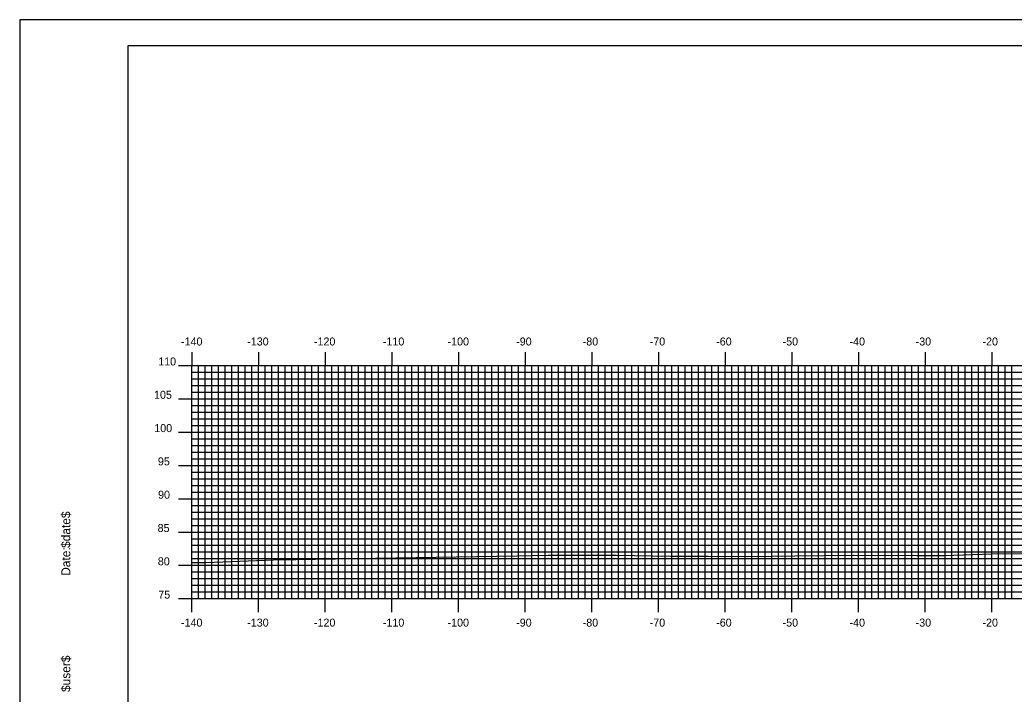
# Model space of a CAD drawing. Extents: x 852542 to 852886, y 364366 to 364586.
# Drawn here: x 852542.4 to 852691.5, y 364484.5 to 364585.7 of the extents above; entities that cross this region are included whole.
import ezdxf

# ---------------------------------------------------------------- set-up
doc = ezdxf.new("R2010")
doc.units = 0
for name, color, linetype in [('BORDER', 7, 'Continuous'), ('H_V ANNOTATION', 7, 'Continuous'), ('MAJOR', 7, 'Continuous'), ('MINOR', 7, 'Continuous'), ('PLOT BOUNDARY', 7, 'Continuous'), ('S_Roadway_Centerline', 7, 'Continuous')]:
    doc.layers.add(name, color=color, linetype=linetype)

msp = doc.modelspace()

# ---------------------------------------------------------------- linework, layer by layer
at = {"layer": 'BORDER'}
msp.add_lwpolyline([(852558.58, 364371.79), (852878.58, 364371.79), (852878.58, 364581.79), (852558.58, 364581.79)], close=True, dxfattribs=at)
at = {"layer": 'MAJOR'}
for p, q in [((852568.18, 364535.79), (852568.18, 364533.79)), ((852578.18, 364535.79), (852578.18, 364533.79)), ((852588.18, 364535.79), (852588.18, 364533.79)), ((852598.18, 364535.79), (852598.18, 364533.79)), ((852608.18, 364535.79), (852608.18, 364533.79)), ((852618.18, 364535.79), (852618.18, 364533.79)), ((852628.18, 364535.79), (852628.18, 364533.79)), ((852638.18, 364535.79), (852638.18, 364533.79)), ((852648.18, 364535.79), (852648.18, 364533.79)), ((852658.18, 364535.79), (852658.18, 364533.79)), ((852668.18, 364535.79), (852668.18, 364533.79)), ((852678.18, 364535.79), (852678.18, 364533.79)), ((852688.18, 364535.79), (852688.18, 364533.79)), ((852566.17, 364533.79), (852568.18, 364533.79)), ((852568.18, 364533.79), (852848.18, 364533.79)), ((852568.18, 364498.79), (852568.18, 364533.79)), ((852568.18, 364498.79), (852568.18, 364533.79)), ((852568.18, 364533.79), (852848.18, 364533.79)), ((852578.18, 364498.79), (852578.18, 364533.79)), ((852588.18, 364498.79), (852588.18, 364533.79)), ((852598.18, 364498.79), (852598.18, 364533.79)), ((852608.18, 364498.79), (852608.18, 364533.79)), ((852618.18, 364498.79), (852618.18, 364533.79)), ((852628.18, 364498.79), (852628.18, 364533.79)), ((852638.18, 364498.79), (852638.18, 364533.79)), ((852648.18, 364498.79), (852648.18, 364533.79)), ((852658.18, 364498.79), (852658.18, 364533.79)), ((852668.18, 364498.79), (852668.18, 364533.79)), ((852678.18, 364498.79), (852678.18, 364533.79)), ((852688.18, 364498.79), (852688.18, 364533.79)), ((852566.17, 364528.79), (852568.18, 364528.79)), ((852568.18, 364528.79), (852848.18, 364528.79)), ((852566.17, 364523.79), (852568.18, 364523.79)), ((852568.18, 364523.79), (852848.18, 364523.79)), ((852566.17, 364518.79), (852568.18, 364518.79)), ((852568.18, 364518.79), (852848.18, 364518.79)), ((852566.17, 364513.79), (852568.18, 364513.79)), ((852568.18, 364513.79), (852848.18, 364513.79)), ((852566.17, 364508.79), (852568.18, 364508.79)), ((852568.18, 364508.79), (852848.18, 364508.79)), ((852566.17, 364503.79), (852568.18, 364503.79)), ((852568.18, 364503.79), (852848.18, 364503.79)), ((852566.17, 364498.79), (852568.18, 364498.79)), ((852568.18, 364498.79), (852848.18, 364498.79)), ((852568.18, 364498.79), (852848.18, 364498.79)), ((852568.18, 364496.78), (852568.18, 364498.79)), ((852578.18, 364496.78), (852578.18, 364498.79)), ((852588.18, 364496.78), (852588.18, 364498.79)), ((852598.18, 364496.78), (852598.18, 364498.79)), ((852608.18, 364496.78), (852608.18, 364498.79)), ((852618.18, 364496.78), (852618.18, 364498.79)), ((852628.18, 364496.78), (852628.18, 364498.79)), ((852638.18, 364496.78), (852638.18, 364498.79)), ((852648.18, 364496.78), (852648.18, 364498.79)), ((852658.18, 364496.78), (852658.18, 364498.79)), ((852668.18, 364496.78), (852668.18, 364498.79)), ((852678.18, 364496.78), (852678.18, 364498.79)), ((852688.18, 364496.78), (852688.18, 364498.79))]:
    msp.add_line(p, q, dxfattribs=at)
at = {"layer": 'MINOR'}
for p, q in [((852569.18, 364498.79), (852569.18, 364533.79)), ((852570.18, 364498.79), (852570.18, 364533.79)), ((852571.18, 364498.79), (852571.18, 364533.79)), ((852572.18, 364498.79), (852572.18, 364533.79)), ((852573.18, 364498.79), (852573.18, 364533.79)), ((852574.18, 364498.79), (852574.18, 364533.79)), ((852575.18, 364498.79), (852575.18, 364533.79)), ((852576.18, 364498.79), (852576.18, 364533.79)), ((852577.18, 364498.79), (852577.18, 364533.79)), ((852579.18, 364498.79), (852579.18, 364533.79)), ((852580.18, 364498.79), (852580.18, 364533.79)), ((852581.18, 364498.79), (852581.18, 364533.79)), ((852582.18, 364498.79), (852582.18, 364533.79)), ((852583.18, 364498.79), (852583.18, 364533.79)), ((852584.18, 364498.79), (852584.18, 364533.79)), ((852585.18, 364498.79), (852585.18, 364533.79)), ((852586.18, 364498.79), (852586.18, 364533.79)), ((852587.18, 364498.79), (852587.18, 364533.79)), ((852589.18, 364498.79), (852589.18, 364533.79)), ((852590.18, 364498.79), (852590.18, 364533.79)), ((852591.18, 364498.79), (852591.18, 364533.79)), ((852592.18, 364498.79), (852592.18, 364533.79)), ((852593.18, 364498.79), (852593.18, 364533.79)), ((852594.18, 364498.79), (852594.18, 364533.79)), ((852595.18, 364498.79), (852595.18, 364533.79)), ((852596.18, 364498.79), (852596.18, 364533.79)), ((852597.18, 364498.79), (852597.18, 364533.79)), ((852599.18, 364498.79), (852599.18, 364533.79)), ((852600.18, 364498.79), (852600.18, 364533.79)), ((852601.18, 364498.79), (852601.18, 364533.79)), ((852602.18, 364498.79), (852602.18, 364533.79)), ((852603.18, 364498.79), (852603.18, 364533.79)), ((852604.18, 364498.79), (852604.18, 364533.79)), ((852605.18, 364498.79), (852605.18, 364533.79)), ((852606.18, 364498.79), (852606.18, 364533.79)), ((852607.18, 364498.79), (852607.18, 364533.79)), ((852609.18, 364498.79), (852609.18, 364533.79)), ((852610.18, 364498.79), (852610.18, 364533.79)), ((852611.18, 364498.79), (852611.18, 364533.79)), ((852612.18, 364498.79), (852612.18, 364533.79)), ((852613.18, 364498.79), (852613.18, 364533.79)), ((852614.18, 364498.79), (852614.18, 364533.79)), ((852615.18, 364498.79), (852615.18, 364533.79)), ((852616.18, 364498.79), (852616.18, 364533.79)), ((852617.18, 364498.79), (852617.18, 364533.79)), ((852619.18, 364498.79), (852619.18, 364533.79)), ((852620.18, 364498.79), (852620.18, 364533.79)), ((852621.18, 364498.79), (852621.18, 364533.79)), ((852622.18, 364498.79), (852622.18, 364533.79)), ((852623.18, 364498.79), (852623.18, 364533.79)), ((852624.18, 364498.79), (852624.18, 364533.79)), ((852625.18, 364498.79), (852625.18, 364533.79)), ((852626.18, 364498.79), (852626.18, 364533.79)), ((852627.18, 364498.79), (852627.18, 364533.79)), ((852629.18, 364498.79), (852629.18, 364533.79)), ((852630.18, 364498.79), (852630.18, 364533.79)), ((852631.18, 364498.79), (852631.18, 364533.79)), ((852632.18, 364498.79), (852632.18, 364533.79)), ((852633.18, 364498.79), (852633.18, 364533.79)), ((852634.18, 364498.79), (852634.18, 364533.79)), ((852635.18, 364498.79), (852635.18, 364533.79)), ((852636.18, 364498.79), (852636.18, 364533.79)), ((852637.18, 364498.79), (852637.18, 364533.79)), ((852639.18, 364498.79), (852639.18, 364533.79)), ((852640.18, 364498.79), (852640.18, 364533.79)), ((852641.18, 364498.79), (852641.18, 364533.79)), ((852642.18, 364498.79), (852642.18, 364533.79)), ((852643.18, 364498.79), (852643.18, 364533.79)), ((852644.18, 364498.79), (852644.18, 364533.79)), ((852645.18, 364498.79), (852645.18, 364533.79)), ((852646.18, 364498.79), (852646.18, 364533.79)), ((852647.18, 364498.79), (852647.18, 364533.79)), ((852649.18, 364498.79), (852649.18, 364533.79)), ((852650.18, 364498.79), (852650.18, 364533.79)), ((852651.18, 364498.79), (852651.18, 364533.79)), ((852652.18, 364498.79), (852652.18, 364533.79)), ((852653.18, 364498.79), (852653.18, 364533.79)), ((852654.18, 364498.79), (852654.18, 364533.79)), ((852655.18, 364498.79), (852655.18, 364533.79)), ((852656.18, 364498.79), (852656.18, 364533.79)), ((852657.18, 364498.79), (852657.18, 364533.79)), ((852659.18, 364498.79), (852659.18, 364533.79)), ((852660.18, 364498.79), (852660.18, 364533.79)), ((852661.18, 364498.79), (852661.18, 364533.79)), ((852662.18, 364498.79), (852662.18, 364533.79)), ((852663.18, 364498.79), (852663.18, 364533.79)), ((852664.18, 364498.79), (852664.18, 364533.79)), ((852665.18, 364498.79), (852665.18, 364533.79)), ((852666.18, 364498.79), (852666.18, 364533.79)), ((852667.18, 364498.79), (852667.18, 364533.79)), ((852669.18, 364498.79), (852669.18, 364533.79)), ((852670.18, 364498.79), (852670.18, 364533.79)), ((852671.18, 364498.79), (852671.18, 364533.79)), ((852672.18, 364498.79), (852672.18, 364533.79)), ((852673.18, 364498.79), (852673.18, 364533.79)), ((852674.18, 364498.79), (852674.18, 364533.79)), ((852675.18, 364498.79), (852675.18, 364533.79)), ((852676.18, 364498.79), (852676.18, 364533.79)), ((852677.18, 364498.79), (852677.18, 364533.79)), ((852679.18, 364498.79), (852679.18, 364533.79)), ((852680.18, 364498.79), (852680.18, 364533.79)), ((852681.18, 364498.79), (852681.18, 364533.79)), ((852682.18, 364498.79), (852682.18, 364533.79)), ((852683.18, 364498.79), (852683.18, 364533.79)), ((852684.18, 364498.79), (852684.18, 364533.79)), ((852685.18, 364498.79), (852685.18, 364533.79)), ((852686.18, 364498.79), (852686.18, 364533.79)), ((852687.18, 364498.79), (852687.18, 364533.79)), ((852689.18, 364498.79), (852689.18, 364533.79)), ((852690.18, 364498.79), (852690.18, 364533.79)), ((852691.18, 364498.79), (852691.18, 364533.79)), ((852568.18, 364532.79), (852848.18, 364532.79)), ((852568.18, 364532.79), (852570.18, 364532.79)), ((852568.18, 364531.79), (852848.18, 364531.79)), ((852568.18, 364531.79), (852570.18, 364531.79)), ((852568.18, 364530.79), (852848.18, 364530.79)), ((852568.18, 364530.79), (852570.18, 364530.79)), ((852568.18, 364529.79), (852848.18, 364529.79)), ((852568.18, 364529.79), (852570.18, 364529.79)), ((852568.18, 364527.79), (852848.18, 364527.79)), ((852568.18, 364527.79), (852570.18, 364527.79)), ((852568.18, 364526.79), (852848.18, 364526.79)), ((852568.18, 364526.79), (852570.18, 364526.79)), ((852568.18, 364525.79), (852848.18, 364525.79)), ((852568.18, 364525.79), (852570.18, 364525.79)), ((852568.18, 364524.79), (852848.18, 364524.79)), ((852568.18, 364524.79), (852570.18, 364524.79)), ((852568.18, 364522.79), (852848.18, 364522.79)), ((852568.18, 364522.79), (852570.18, 364522.79)), ((852568.18, 364521.79), (852848.18, 364521.79)), ((852568.18, 364521.79), (852570.18, 364521.79)), ((852568.18, 364520.79), (852848.18, 364520.79)), ((852568.18, 364520.79), (852570.18, 364520.79)), ((852568.18, 364519.79), (852848.18, 364519.79)), ((852568.18, 364519.79), (852570.18, 364519.79)), ((852568.18, 364517.79), (852848.18, 364517.79)), ((852568.18, 364517.79), (852570.18, 364517.79)), ((852568.18, 364516.79), (852848.18, 364516.79)), ((852568.18, 364516.79), (852570.18, 364516.79)), ((852568.18, 364515.79), (852848.18, 364515.79)), ((852568.18, 364515.79), (852570.18, 364515.79)), ((852568.18, 364514.79), (852848.18, 364514.79)), ((852568.18, 364514.79), (852570.18, 364514.79)), ((852568.18, 364512.79), (852848.18, 364512.79)), ((852568.18, 364512.79), (852570.18, 364512.79)), ((852568.18, 364511.79), (852848.18, 364511.79)), ((852568.18, 364511.79), (852570.18, 364511.79)), ((852568.18, 364510.79), (852848.18, 364510.79)), ((852568.18, 364510.79), (852570.18, 364510.79)), ((852568.18, 364509.79), (852848.18, 364509.79)), ((852568.18, 364509.79), (852570.18, 364509.79)), ((852568.18, 364507.79), (852848.18, 364507.79)), ((852568.18, 364507.79), (852570.18, 364507.79)), ((852568.18, 364506.79), (852848.18, 364506.79)), ((852568.18, 364506.79), (852570.18, 364506.79)), ((852568.18, 364505.79), (852848.18, 364505.79)), ((852568.18, 364505.79), (852570.18, 364505.79)), ((852568.18, 364504.79), (852848.18, 364504.79)), ((852568.18, 364504.79), (852570.18, 364504.79)), ((852568.18, 364502.79), (852848.18, 364502.79)), ((852568.18, 364502.79), (852570.18, 364502.79)), ((852568.18, 364501.79), (852848.18, 364501.79)), ((852568.18, 364501.79), (852570.18, 364501.79)), ((852568.18, 364500.79), (852848.18, 364500.79)), ((852568.18, 364500.79), (852570.18, 364500.79)), ((852568.18, 364499.79), (852848.18, 364499.79)), ((852568.18, 364499.79), (852570.18, 364499.79))]:
    msp.add_line(p, q, dxfattribs=at)
at = {"layer": 'PLOT BOUNDARY'}
msp.add_lwpolyline([(852542.39, 364365.67), (852882.39, 364365.67), (852882.39, 364585.67), (852542.39, 364585.67)], close=True, dxfattribs=at)
at = {"layer": 'S_Roadway_Centerline'}
msp.add_lwpolyline([(852568.18, 364504.19), (852570.28, 364504.2), (852580.43, 364504.6), (852582.65, 364504.64), (852583.76, 364504.66), (852586.71, 364504.69), (852607.84, 364505.06), (852616.94, 364505.21), (852621.6, 364505.29), (852631.82, 364505.31), (852640.01, 364505.18), (852645.65, 364505.18), (852651.57, 364505.11), (852658.62, 364505.19), (852667.39, 364505.33), (852676.92, 364505.26), (852681, 364505.24), (852688.24, 364505.51), (852704.86, 364505.68)], dxfattribs=at)

# ---------------------------------------------------------------- texts
at = {"layer": 'BORDER'}
for s, p in [('$date$', (852549.95, 364506.4)), ('Date:', (852549.95, 364502.22)), ('$user$', (852549.95, 364484.77))]:
    msp.add_text(s, height=1.339, rotation=90, dxfattribs=at).set_placement(p)
at = {"layer": 'H_V ANNOTATION'}
for s, p in [('-140', (852566.56, 364536.79)), ('-130', (852576.49, 364536.79)), ('-120', (852586.5, 364536.79)), ('-110', (852596.84, 364536.79)), ('-100', (852606.54, 364536.79)), ('-90', (852616.83, 364536.79)), ('-80', (852626.81, 364536.79)), ('-70', (852636.86, 364536.79)), ('-60', (852646.83, 364536.79)), ('-50', (852656.79, 364536.79)), ('-40', (852666.83, 364536.79)), ('-30', (852676.75, 364536.79)), ('-20', (852686.77, 364536.79)), ('110', (852563.14, 364533.79)), ('105', (852562.51, 364528.79)), ('100', (852562.55, 364523.79)), ('95', (852563.09, 364518.79)), ('90', (852563.12, 364513.79)), ('85', (852563.05, 364508.79)), ('80', (852563.08, 364503.79)), ('75', (852563.15, 364498.79)), ('-140', (852566.56, 364494.59)), ('-130', (852576.49, 364494.59)), ('-120', (852586.5, 364494.59)), ('-110', (852596.84, 364494.59)), ('-100', (852606.54, 364494.59)), ('-90', (852616.83, 364494.59)), ('-80', (852626.81, 364494.59)), ('-70', (852636.86, 364494.59)), ('-60', (852646.83, 364494.59)), ('-50', (852656.79, 364494.59)), ('-40', (852666.83, 364494.59)), ('-30', (852676.75, 364494.59)), ('-20', (852686.77, 364494.59))]:
    msp.add_text(s, height=1.2, dxfattribs=at).set_placement(p)
at = {"layer": 'MAJOR'}
msp.add_text('-', height=0.012, dxfattribs=at).set_placement((852568.17, 364498.79))

doc.saveas('drawing.dxf')
